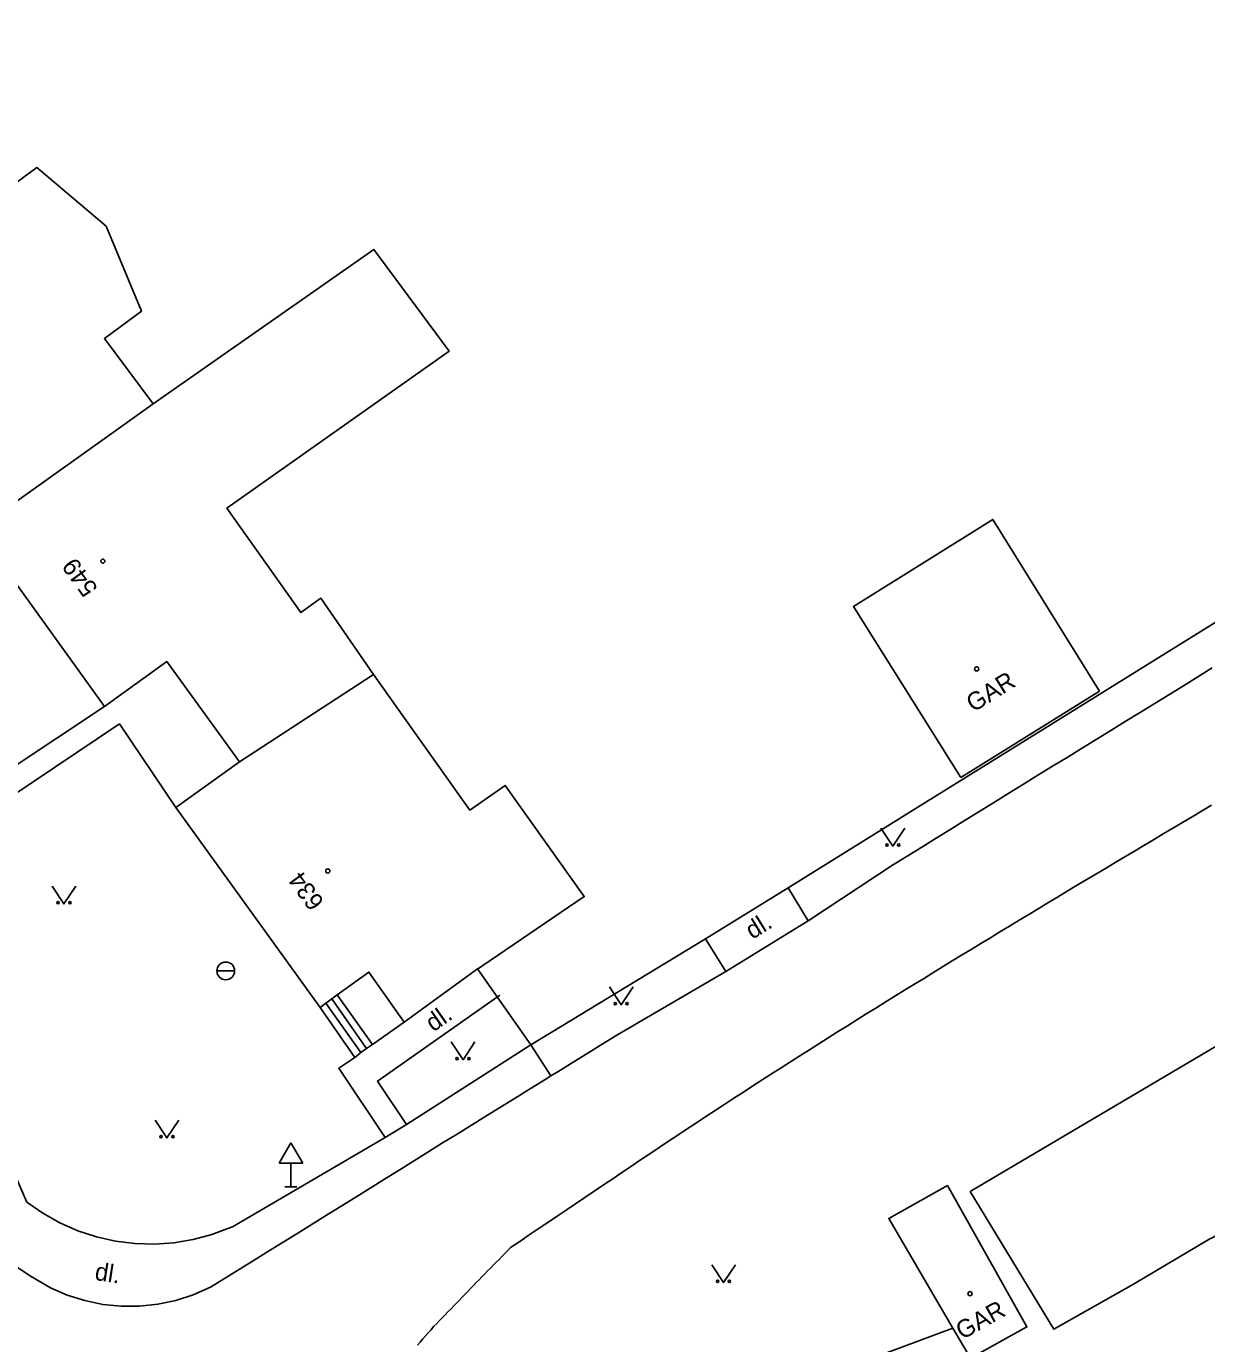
# Model space of a CAD drawing. Extents: x -545714 to -535419, y -1201788 to -1194297.
# Drawn here: x -535548.5 to -535498.7, y -1201544.3 to -1201488.6 of the extents above; entities that cross this region are included whole.
import ezdxf

# ---------------------------------------------------------------- set-up
doc = ezdxf.new("R2010")
doc.units = 0
for name, color, linetype in [('Vrstva 10', 7, 'Continuous'), ('Vrstva 11', 7, 'Continuous'), ('Vrstva 15', 7, 'Continuous'), ('Vrstva 3', 7, 'Continuous'), ('Vrstva 4', 7, 'Continuous'), ('Vrstva 5', 7, 'Continuous'), ('Vrstva 8', 7, 'Continuous'), ('Vrstva 9', 7, 'Continuous')]:
    doc.layers.add(name, color=color, linetype=linetype)

msp = doc.modelspace()

# ---------------------------------------------------------------- linework, layer by layer
at = {"layer": 'Vrstva 10'}
for p, q in [((-535540.475, -1201528.52), (-535539.725, -1201528.52)), ((-535537.35, -1201535.774), (-535537.85, -1201536.64)), ((-535537.35, -1201535.774), (-535536.85, -1201536.64)), ((-535537.85, -1201536.64), (-535536.85, -1201536.64)), ((-535537.35, -1201537.64), (-535537.35, -1201536.64)), ((-535537.6, -1201537.64), (-535537.1, -1201537.64))]:
    msp.add_line(p, q, dxfattribs=at)
for points in [[(-535467.2, -1201488.64), (-535464.59, -1201492.87), (-535510.99, -1201521.68)], [(-535510.99, -1201521.68), (-535516.35, -1201525.01), (-535519.84, -1201527.16), (-535527.22, -1201531.64)], [(-535527.22, -1201531.64), (-535529.47, -1201528.44)], [(-535509.4, -1201543.6), (-535512.88, -1201544.9), (-535514.03, -1201548.76)]]:
    msp.add_lwpolyline(points, dxfattribs=at)
msp.add_circle((-535540.1, -1201528.52), 0.375, dxfattribs=at)
at = {"layer": 'Vrstva 11'}
for points in [[(-535498.44, -1201515.73), (-535499.05, -1201516.11), (-535499.66, -1201516.48), (-535500.28, -1201516.86), (-535500.89, -1201517.24), (-535501.51, -1201517.62), (-535502.12, -1201517.99), (-535502.73, -1201518.37), (-535503.35, -1201518.75), (-535503.96, -1201519.13), (-535504.57, -1201519.51), (-535505.19, -1201519.88), (-535505.8, -1201520.26), (-535506.41, -1201520.64), (-535507.03, -1201521.02), (-535507.64, -1201521.4), (-535508.25, -1201521.77), (-535508.87, -1201522.15), (-535509.48, -1201522.53), (-535510.1, -1201522.91), (-535510.71, -1201523.29), (-535511.32, -1201523.67), (-535511.94, -1201524.05), (-535515.5, -1201526.41)], [(-535555.04, -1201523.88), (-535545.22, -1201517.36)], [(-535554.6, -1201524.8), (-535544.59, -1201518.09), (-535542.21, -1201521.62)], [(-535498.48, -1201521.52), (-535498.89, -1201521.77), (-535499.29, -1201522.01), (-535499.7, -1201522.25), (-535500.11, -1201522.49), (-535500.51, -1201522.74), (-535500.92, -1201522.98), (-535501.33, -1201523.22), (-535501.73, -1201523.46), (-535502.14, -1201523.71), (-535502.54, -1201523.95), (-535502.95, -1201524.19), (-535503.36, -1201524.43), (-535503.76, -1201524.68), (-535504.17, -1201524.92), (-535504.57, -1201525.16), (-535504.98, -1201525.41), (-535505.39, -1201525.65), (-535505.79, -1201525.9), (-535506.19, -1201526.14), (-535506.6, -1201526.38), (-535507.01, -1201526.63), (-535507.41, -1201526.87), (-535507.81, -1201527.12), (-535508.22, -1201527.37), (-535508.62, -1201527.61), (-535509.03, -1201527.86), (-535509.43, -1201528.1), (-535509.83, -1201528.35), (-535510.24, -1201528.6), (-535510.64, -1201528.85), (-535511.04, -1201529.09), (-535511.44, -1201529.34), (-535511.85, -1201529.59), (-535512.25, -1201529.84), (-535512.65, -1201530.09), (-535513.05, -1201530.34), (-535513.45, -1201530.59), (-535513.85, -1201530.84), (-535514.26, -1201531.09), (-535514.66, -1201531.34), (-535515.06, -1201531.6), (-535515.45, -1201531.85), (-535515.85, -1201532.1), (-535516.25, -1201532.36), (-535516.65, -1201532.61)], [(-535533.37, -1201535.56), (-535539.82, -1201539.32), (-535539.9, -1201539.36), (-535540.68, -1201539.65), (-535541.47, -1201539.86), (-535542.29, -1201540), (-535543.11, -1201540.06), (-535543.94, -1201540.03), (-535544.76, -1201539.93), (-535545.56, -1201539.75), (-535546.35, -1201539.49), (-535547.1, -1201539.16), (-535547.82, -1201538.75), (-535548.5, -1201538.28), (-535551.9, -1201530.48), (-535554.6, -1201524.8)], [(-535515.5, -1201526.41), (-535516.35, -1201525.01)], [(-535515.5, -1201526.41), (-535518.98, -1201528.55)], [(-535518.98, -1201528.55), (-535519.84, -1201527.16)], [(-535518.98, -1201528.55), (-535523.59, -1201531.24), (-535524.2, -1201531.62), (-535524.81, -1201531.99), (-535525.43, -1201532.37), (-535526.04, -1201532.75), (-535526.37, -1201532.95)], [(-535535.39, -1201529.53), (-535533.9, -1201531.63)], [(-535528.53, -1201529.55), (-535533.69, -1201533.17), (-535532.46, -1201535.01)], [(-535536.11, -1201530.06), (-535534.65, -1201532.18), (-535534.39, -1201531.97)], [(-535535.87, -1201529.88), (-535534.39, -1201531.97)], [(-535535.62, -1201529.7), (-535534.15, -1201531.8)], [(-535533.9, -1201531.63), (-535532.56, -1201530.68)], [(-535534.39, -1201531.97), (-535534.15, -1201531.8)], [(-535534.15, -1201531.8), (-535533.9, -1201531.63)], [(-535527.22, -1201531.64), (-535532.46, -1201535.01)], [(-535526.37, -1201532.95), (-535527.22, -1201531.64)], [(-535534.65, -1201532.18), (-535535.33, -1201532.63), (-535533.37, -1201535.56)], [(-535526.37, -1201532.95), (-535526.66, -1201533.13), (-535527.27, -1201533.51), (-535527.88, -1201533.89), (-535528.49, -1201534.27), (-535529.11, -1201534.65), (-535529.72, -1201535.03), (-535530.33, -1201535.41), (-535530.94, -1201535.78), (-535531.56, -1201536.17), (-535532.17, -1201536.55), (-535532.78, -1201536.93), (-535533.39, -1201537.31), (-535534, -1201537.69), (-535534.61, -1201538.07), (-535535.23, -1201538.45), (-535535.84, -1201538.83), (-535536.45, -1201539.21), (-535537.06, -1201539.59), (-535537.68, -1201539.97), (-535538.29, -1201540.35), (-535538.9, -1201540.73), (-535540.74, -1201541.87), (-535541.47, -1201542.2), (-535542.21, -1201542.43), (-535542.97, -1201542.59), (-535543.74, -1201542.68), (-535544.52, -1201542.68), (-535545.29, -1201542.6), (-535546.05, -1201542.44), (-535546.79, -1201542.21), (-535547.5, -1201541.9), (-535548.32, -1201541.43), (-535549.11, -1201540.9)], [(-535516.65, -1201532.61), (-535517.05, -1201532.87), (-535517.45, -1201533.12), (-535517.84, -1201533.38), (-535518.24, -1201533.64), (-535518.64, -1201533.89), (-535519.03, -1201534.15), (-535519.43, -1201534.41), (-535519.82, -1201534.67), (-535520.22, -1201534.93), (-535520.61, -1201535.19), (-535521.01, -1201535.45), (-535521.4, -1201535.71), (-535521.8, -1201535.98), (-535522.19, -1201536.24), (-535522.58, -1201536.5), (-535522.97, -1201536.77), (-535523.37, -1201537.03), (-535523.76, -1201537.3), (-535524.15, -1201537.56), (-535524.54, -1201537.82), (-535524.93, -1201538.09), (-535525.33, -1201538.35), (-535525.72, -1201538.62), (-535526.11, -1201538.88), (-535526.5, -1201539.15), (-535526.9, -1201539.41), (-535527.29, -1201539.67), (-535527.68, -1201539.94), (-535528.07, -1201540.2), (-535528.19, -1201540.33), (-535528.31, -1201540.45), (-535528.43, -1201540.57), (-535528.55, -1201540.7), (-535528.68, -1201540.82), (-535528.8, -1201540.94), (-535528.92, -1201541.07), (-535529.04, -1201541.19), (-535529.16, -1201541.31), (-535529.28, -1201541.44), (-535529.4, -1201541.56), (-535529.52, -1201541.68), (-535529.64, -1201541.81), (-535529.76, -1201541.93), (-535529.88, -1201542.06), (-535530, -1201542.18), (-535530.12, -1201542.3), (-535530.24, -1201542.43), (-535530.36, -1201542.55), (-535530.48, -1201542.67), (-535530.6, -1201542.8), (-535530.72, -1201542.92), (-535530.84, -1201543.04), (-535530.96, -1201543.17), (-535531.08, -1201543.29), (-535531.2, -1201543.42), (-535531.32, -1201543.54), (-535531.43, -1201543.67), (-535531.55, -1201543.8), (-535531.66, -1201543.93), (-535531.78, -1201544.06), (-535531.89, -1201544.19), (-535532, -1201544.32)], [(-535532.46, -1201535.01), (-535533.37, -1201535.56)]]:
    msp.add_lwpolyline(points, dxfattribs=at)
at = {"layer": 'Vrstva 3'}
for points in [[(-535512.43, -1201522.5), (-535511.93, -1201523.25), (-535511.43, -1201522.5)], [(-535547.43, -1201524.94), (-535546.93, -1201525.69), (-535546.43, -1201524.94)], [(-535523.9, -1201529.2), (-535523.4, -1201529.95), (-535522.9, -1201529.2)], [(-535530.58, -1201531.52), (-535530.08, -1201532.27), (-535529.58, -1201531.52)], [(-535543.08, -1201534.82), (-535542.58, -1201535.57), (-535542.08, -1201534.82)], [(-535519.58, -1201540.93), (-535519.08, -1201541.68), (-535518.58, -1201540.93)]]:
    msp.add_lwpolyline(points, dxfattribs=at)
for centre in [(-535512.18, -1201523.2), (-535511.68, -1201523.2), (-535547.18, -1201525.64), (-535546.68, -1201525.64), (-535523.65, -1201529.9), (-535523.15, -1201529.9), (-535530.33, -1201532.22), (-535529.83, -1201532.22), (-535542.83, -1201535.52), (-535542.33, -1201535.52), (-535519.33, -1201541.63), (-535518.83, -1201541.63)]:
    msp.add_circle(centre, 0.05, dxfattribs=at)
at = {"layer": 'Vrstva 4'}
for points in [[(-535508.66, -1201537.84), (-535452.84, -1201504.86)], [(-535550.61, -1201509.88), (-535545.22, -1201517.36), (-535542.59, -1201515.46), (-535539.52, -1201519.7)], [(-535509.06, -1201520.36), (-535503.2, -1201516.71)], [(-535539.52, -1201519.7), (-535542.21, -1201521.62), (-535536.11, -1201530.06)], [(-535532.56, -1201530.68), (-535529.47, -1201528.44)], [(-535529.47, -1201528.44), (-535529.39, -1201528.39)], [(-535529.39, -1201528.39), (-535529.25, -1201528.29)], [(-535535.39, -1201529.53), (-535534.05, -1201528.57), (-535532.56, -1201530.68)], [(-535535.62, -1201529.7), (-535535.39, -1201529.53)], [(-535536.11, -1201530.06), (-535535.87, -1201529.88)], [(-535535.87, -1201529.88), (-535535.62, -1201529.7)], [(-535509.4, -1201543.6), (-535512.1, -1201538.97), (-535509.62, -1201537.58)]]:
    msp.add_lwpolyline(points, dxfattribs=at)
at = {"layer": 'Vrstva 5'}
for points in [[(-535543.17, -1201504.58), (-535545.22, -1201501.82), (-535543.66, -1201500.66), (-535545.15, -1201497.07), (-535548.08, -1201494.6), (-535549.58, -1201495.71), (-535551.65, -1201492.83), (-535559.12, -1201498.12)], [(-535533.86, -1201516), (-535536.09, -1201512.79), (-535536.93, -1201513.39), (-535540.05, -1201508.98), (-535530.66, -1201502.35), (-535533.84, -1201498.06), (-535543.17, -1201504.58), (-535550.61, -1201509.88)], [(-535508.66, -1201537.84), (-535505.13, -1201543.65), (-535501.77, -1201541.75), (-535498.54, -1201539.84), (-535498.42, -1201539.77), (-535495.44, -1201538), (-535492.35, -1201536.17), (-535491.12, -1201535.44), (-535489.25, -1201534.34), (-535486.15, -1201532.5), (-535482.92, -1201530.59), (-535479.86, -1201528.78), (-535476.81, -1201526.97), (-535473.75, -1201525.16), (-535470.7, -1201523.36), (-535467.64, -1201521.55), (-535464.59, -1201519.74), (-535461.53, -1201517.93), (-535458.48, -1201516.12), (-535455.42, -1201514.31), (-535452.37, -1201512.51), (-535449.32, -1201510.7), (-535452.84, -1201504.86)], [(-535503.2, -1201516.71), (-535507.71, -1201509.46), (-535513.59, -1201513.13), (-535509.06, -1201520.36)], [(-535533.86, -1201516), (-535539.52, -1201519.7)], [(-535529.25, -1201528.29), (-535524.96, -1201525.38), (-535528.3, -1201520.69), (-535529.79, -1201521.74), (-535533.86, -1201516)], [(-535509.4, -1201543.6), (-535508.65, -1201544.87), (-535506.27, -1201543.55), (-535509.62, -1201537.58)]]:
    msp.add_lwpolyline(points, dxfattribs=at)
at = {"layer": 'Vrstva 9'}
for centre in [(-535545.29, -1201511.22), (-535508.39, -1201515.77), (-535535.79, -1201524.3), (-535508.67, -1201542.15)]:
    msp.add_circle(centre, 0.0875, dxfattribs=at)

# ---------------------------------------------------------------- texts
at = {"layer": 'Vrstva 15'}
for s, rotation, p in [('GAR', 31.88, (-535508.53, -1201517.62)), ('dl.', 31.71, (-535517.86, -1201527.21)), ('dl.', 35.05, (-535531.33, -1201531.12)), ('dl.', 351.09, (-535545.66, -1201541.56)), ('GAR', 29.28, (-535509, -1201544.11))]:
    msp.add_text(s, height=0.75, rotation=rotation, dxfattribs=at).set_placement(p)
at = {"layer": 'Vrstva 8'}
for s, rotation, p in [('549', 125.82, (-535545.47, -1201512.37)), ('634', 125.84, (-535535.91, -1201525.61))]:
    msp.add_text(s, height=0.75, rotation=rotation, dxfattribs=at).set_placement(p)

doc.saveas('drawing.dxf')
